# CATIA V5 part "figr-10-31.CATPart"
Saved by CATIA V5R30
Part number: Part1
Bounding box of the stored display mesh (mm): x -84 to 53, y -93.367 to 104.555, z -56.529 to 41.172
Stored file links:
  D:\PROJECTS\CATIA V56R 2020\Resources\Parts File\c10_catia_v5_6r2020_prt\figr-10-31.CATPart
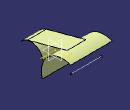
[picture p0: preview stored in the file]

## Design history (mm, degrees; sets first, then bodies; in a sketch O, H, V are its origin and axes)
Body1 (main body)
  Sketch1 on yz-plane, origin (0, 0, 0), H (0, 1, 0), V (0, 0, 1)
    arc A1 centre (-59.8904, -36.5447) radius 41.17 from (-93.3668, -12.5802) to (-23.896, -56.5291) cw
  Extrude1: Element1 Sketch1, Lim1 20, Lim2 42
  Sketch2 on yz-plane, origin (0, 0, 0), H (0, 1, 0), V (0, 0, 1)
    arc A1 centre (78.3128, -29.0048) radius 70.3421 from (104.5554, 36.2588) to (11.1367, -49.8706) ccw
  Extrude2: Element1 Sketch2, Lim1 53, Lim2 84
  Sketch3 on xy-plane, origin (0, 0, 0), H (1, 0, 0), V (0, 1, 0)
    line L1 (-58.0902, 93.9265) -> (40.4277, 93.9265)
    horizontal: L1 H
  Sweep1: type Segment, GuideSurf (Extrude1; Extrude2), Spine Sketch3, Length1 20, Length2 0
